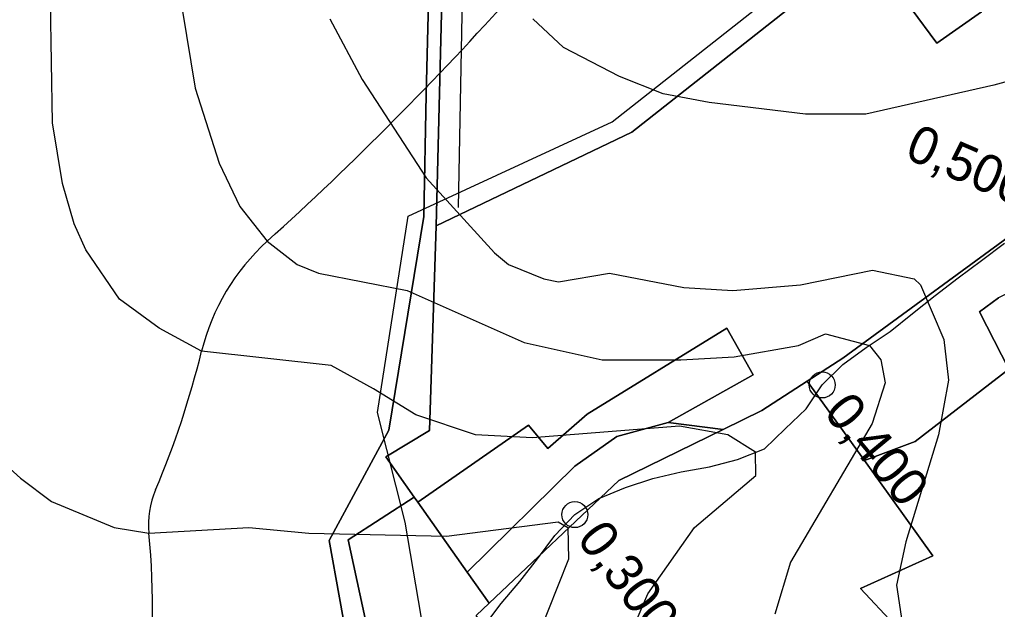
# Model space of a CAD drawing. Extents: x -510989 to -501240, y -1184665 to -1176089.
# Drawn here: x -510047.2 to -509708.8, y -1177583.4 to -1177379.3 of the extents above; entities that cross this region are included whole.
import ezdxf

# ---------------------------------------------------------------- set-up
doc = ezdxf.new("R2010")
doc.units = 0
for name, color, linetype in [('lesni_pozemek', 7, 'Continuous'), ('NAVRH_interakcni_prvky', 7, 'Continuous'), ('NAVRH_rozvodnice', 7, 'Continuous'), ('orna_puda', 7, 'Continuous'), ('ostatni_plocha_x_neplodna_puda', 7, 'Continuous'), ('ostatni_plocha_x_ostatni_komunikace', 7, 'Continuous'), ('STAV_systematicke_odvodneni', 7, 'Continuous'), ('trasovani_toku', 7, 'Continuous'), ('trvaly_travni_porost', 7, 'Continuous'), ('vrstevnice_01', 7, 'Continuous'), ('vrstevnice_02', 7, 'Continuous')]:
    doc.layers.add(name, color=color, linetype=linetype)

msp = doc.modelspace()

# ---------------------------------------------------------------- linework, layer by layer
at = {"layer": 'lesni_pozemek'}
for points in [[(-509631, -1177375.54), (-509666.85, -1177393), (-509662.19, -1177399.04), (-509661.92, -1177399.66), (-509680.94, -1177416.84), (-509697.38, -1177448.86), (-509762.27, -1177496.39), (-509774.65, -1177504.38), (-509790.33, -1177514.5), (-509803.69, -1177521.05), (-509822.77, -1177518.7), (-509793.37, -1177502.17), (-509802.43, -1177486.07), (-509850.77, -1177515.75), (-509864.33, -1177527.68), (-509871.08, -1177519.58), (-509909.37, -1177546.26), (-509910.59, -1177544.53), (-509920.45, -1177530.57), (-509905.31, -1177521.45), (-509903.04, -1177450.59), (-509835.36, -1177418.23), (-509751.69, -1177352.23)], [(-509738.62, -1177375.49), (-509729.77, -1177387.4), (-509714.36, -1177376.56)]]:
    msp.add_lwpolyline(points, dxfattribs=at)
msp.add_lwpolyline([(-509774.65, -1177504.38), (-509754.82, -1177531.88), (-509731.1, -1177564.78), (-509756.2, -1177576.17), (-509744.57, -1177588.61), (-509743.5, -1177592.06), (-509744.51, -1177592.95), (-509813.59, -1177626.16), (-509833.49, -1177635.63), (-509833.73, -1177635.07), (-509845.97, -1177640.31), (-509843.9, -1177645.16), (-509847.08, -1177646.52), (-509847.22, -1177643.51), (-509889.18, -1177585.43), (-509884.7, -1177581.2), (-509839.79, -1177538.76), (-509803.69, -1177521.05), (-509790.33, -1177514.5)], close=True, dxfattribs=at)
at = {"layer": 'NAVRH_interakcni_prvky'}
msp.add_line((-509892, -1177261.75), (-509895.38, -1177444.26), dxfattribs=at)
at = {"layer": 'NAVRH_rozvodnice'}
for centre, radius, start, end in [((-510726.34, -1176610.57), 1140.06, 312.13471, 318.23054), ((-509910.8, -1177512.04), 75.57, 132.1347, 166.1887), ((-510294.96, -1177417.6), 320.03, 337.1311, 346.1887), ((-509971.35, -1177554.1), 31.2, 157.1311, 185.3427), ((-510283.91, -1177583.33), 282.73, 352.9555, 5.3427), ((-509791.78, -1177499.16), 123.67, 297.3565, 320.3942)]:
    msp.add_arc(centre, radius, start, end, dxfattribs=at)
at = {"layer": 'orna_puda'}
for points in [[(-509751.69, -1177352.23), (-509835.36, -1177418.23), (-509903.04, -1177450.59), (-509898.13, -1177257.43)], [(-509903.08, -1177271.99), (-509906.47, -1177405.26), (-509907.24, -1177447.42), (-509919.35, -1177521.3), (-509940.02, -1177559.56), (-509932.88, -1177599.21), (-509966.13, -1177637.97), (-509980.54, -1177661.84), (-509986.51, -1177693.69), (-510011.12, -1177708.83), (-510046.21, -1177724.59), (-510065.83, -1177729.25), (-510067.57, -1177729.21), (-510116.51, -1177610.57), (-510123.38, -1177588.75), (-510123.04, -1177446.95), (-510102.14, -1177427.79), (-510084.34, -1177409.75), (-510084.36, -1177388.11), (-510071.74, -1177384.51), (-510072, -1177373.55)]]:
    msp.add_lwpolyline(points, dxfattribs=at)
at = {"layer": 'ostatni_plocha_x_neplodna_puda'}
for points in [[(-509636.26, -1177329.52), (-509714.36, -1177376.56), (-509729.77, -1177387.4), (-509738.62, -1177375.49), (-509736.13, -1177373.95), (-509643.81, -1177316.99)], [(-509803.69, -1177521.05), (-509839.79, -1177538.76), (-509884.7, -1177581.2), (-509892.27, -1177570.48), (-509855.08, -1177533.79), (-509840.53, -1177523.5), (-509822.77, -1177518.7)]]:
    msp.add_lwpolyline(points, close=True, dxfattribs=at)
at = {"layer": 'ostatni_plocha_x_ostatni_komunikace'}
for points in [[(-509898.13, -1177257.43), (-509903.04, -1177450.59), (-509905.31, -1177521.45), (-509920.45, -1177530.57), (-509910.59, -1177544.53), (-509933.52, -1177559.31), (-509924.48, -1177600.95)], [(-509932.88, -1177599.21), (-509940.02, -1177559.56), (-509919.35, -1177521.3), (-509907.24, -1177447.42), (-509906.47, -1177405.26), (-509903.08, -1177271.99)]]:
    msp.add_lwpolyline(points, dxfattribs=at)
at = {"layer": 'STAV_systematicke_odvodneni'}
for p, q in [((-509842.09, -1177414.7), (-509753.36, -1177344.65)), ((-509912.65, -1177447.32), (-509842.09, -1177414.7)), ((-509923.34, -1177515.24), (-509912.65, -1177447.32)), ((-509913.72, -1177553.2), (-509923.34, -1177515.24)), ((-509902.49, -1177619.51), (-509913.72, -1177553.2))]:
    msp.add_line(p, q, dxfattribs=at)
at = {"layer": 'trasovani_toku'}
for p, q in [((-509714.35, -1177462.66), (-509706.4, -1177456.59)), ((-509722.38, -1177468.62), (-509714.35, -1177462.66)), ((-509730.31, -1177474.71), (-509722.38, -1177468.62)), ((-509738.15, -1177480.92), (-509730.31, -1177474.71)), ((-509745.96, -1177487.17), (-509738.15, -1177480.92)), ((-509754.28, -1177492.72), (-509745.96, -1177487.17)), ((-509762.35, -1177498.62), (-509754.28, -1177492.72)), ((-509769.42, -1177505.7), (-509762.35, -1177498.62)), ((-509774.99, -1177514), (-509769.42, -1177505.7)), ((-509782.25, -1177520.87), (-509774.99, -1177514)), ((-509789.42, -1177527.85), (-509782.25, -1177520.87)), ((-509798.75, -1177531.43), (-509789.42, -1177527.85)), ((-509808.4, -1177534.06), (-509798.75, -1177531.43)), ((-509818.25, -1177535.78), (-509808.4, -1177534.06)), ((-509837.49, -1177541.15), (-509827.99, -1177538.03)), ((-509827.99, -1177538.03), (-509818.25, -1177535.78)), ((-509846.76, -1177544.93), (-509837.49, -1177541.15)), ((-509855.02, -1177550.56), (-509846.76, -1177544.93)), ((-509861.91, -1177557.8), (-509855.02, -1177550.56)), ((-509867.92, -1177565.8), (-509861.91, -1177557.8)), ((-509874.1, -1177573.66), (-509867.92, -1177565.8)), ((-509880.56, -1177581.29), (-509874.1, -1177573.66)), ((-509886.58, -1177589.28), (-509880.56, -1177581.29))]:
    msp.add_line(p, q, dxfattribs=at)
for centre in [(-509769.42, -1177505.7), (-509855.02, -1177550.56)]:
    msp.add_circle(centre, 4.5, dxfattribs=at)
at = {"layer": 'trvaly_travni_porost'}
for points in [[(-509661.92, -1177399.66), (-509643.12, -1177442.55), (-509633.68, -1177445.21), (-509611.17, -1177445.97), (-509589.76, -1177453.23), (-509546.91, -1177453.53), (-509568.76, -1177455.65), (-509586.79, -1177457.4), (-509599.68, -1177456.28), (-509596.6, -1177463.39), (-509627.43, -1177456.33), (-509637.9, -1177458.29), (-509642.03, -1177451.61), (-509660.52, -1177452), (-509708.48, -1177475.5), (-509715.05, -1177480.43), (-509704.91, -1177500.28), (-509737.25, -1177525.22), (-509754.82, -1177531.88), (-509774.65, -1177504.38), (-509762.27, -1177496.39), (-509697.38, -1177448.86), (-509680.94, -1177416.84)], [(-509793.37, -1177502.17), (-509822.77, -1177518.7), (-509840.53, -1177523.5), (-509855.08, -1177533.79), (-509892.27, -1177570.48), (-509909.37, -1177546.26), (-509871.08, -1177519.58), (-509864.33, -1177527.68), (-509850.77, -1177515.75), (-509802.43, -1177486.07)]]:
    msp.add_lwpolyline(points, close=True, dxfattribs=at)
for points in [[(-509678.3, -1177635.13), (-509719.86, -1177643.27), (-509792.23, -1177678.3), (-509813.59, -1177626.16), (-509744.51, -1177592.95), (-509743.5, -1177592.06), (-509744.57, -1177588.61), (-509756.2, -1177576.17), (-509731.1, -1177564.78), (-509754.82, -1177531.88), (-509737.25, -1177525.22), (-509704.91, -1177500.28), (-509715.05, -1177480.43), (-509708.48, -1177475.5)], [(-509924.48, -1177600.95), (-509933.52, -1177559.31), (-509910.59, -1177544.53), (-509909.37, -1177546.26), (-509892.27, -1177570.48), (-509884.7, -1177581.2), (-509889.18, -1177585.43)]]:
    msp.add_lwpolyline(points, dxfattribs=at)
at = {"layer": 'vrstevnice_01'}
for points in [[(-509993.81, -1177358), (-509986.41, -1177403), (-509978.09, -1177429), (-509970.91, -1177444), (-509961.5, -1177456), (-509951.09, -1177464), (-509943.69, -1177467), (-509913, -1177473), (-509872.59, -1177491), (-509845.59, -1177497), (-509818.31, -1177497), (-509799.91, -1177496), (-509777.69, -1177492), (-509768.31, -1177488), (-509753.09, -1177492), (-509749.19, -1177497), (-509747.69, -1177505), (-509752.19, -1177519), (-509780.41, -1177567), (-509785.81, -1177585)], [(-509655.19, -1177387), (-509710.09, -1177402), (-509754.31, -1177412), (-509775.19, -1177412), (-509808.5, -1177408), (-509824.5, -1177405), (-509839.59, -1177399), (-509858.91, -1177389), (-509869.59, -1177379)], [(-510059.09, -1177527), (-510046.81, -1177538), (-510036.09, -1177546), (-510014.41, -1177555), (-510002.41, -1177557), (-509967.81, -1177555), (-509947.09, -1177557), (-509899.41, -1177558), (-509860.81, -1177553), (-509857.41, -1177555), (-509857.19, -1177566), (-509871.5, -1177602), (-509874.5, -1177614), (-509873.91, -1177636), (-509864.31, -1177662), (-509854.19, -1177680), (-509839.41, -1177701), (-509830.19, -1177712), (-509824.59, -1177716), (-509798.41, -1177725), (-509768.31, -1177727), (-509712.91, -1177726), (-509697.5, -1177729)]]:
    msp.add_lwpolyline(points, dxfattribs=at)
at = {"layer": 'vrstevnice_02'}
for points in [[(-509834.5, -1177589), (-509829.81, -1177578), (-509813.59, -1177555), (-509792.41, -1177537), (-509792.5, -1177529), (-509802.09, -1177523), (-509818.81, -1177520), (-509869.69, -1177524), (-509889.41, -1177523), (-509910, -1177516), (-509924.69, -1177507), (-509939.31, -1177499), (-509984.19, -1177494), (-509998.91, -1177486), (-510012.59, -1177476), (-510024.19, -1177459), (-510028.31, -1177450), (-510032.31, -1177436), (-510035.81, -1177415), (-510036.5, -1177373)], [(-509939.81, -1177379), (-509928.59, -1177400), (-509906.5, -1177434), (-509882.81, -1177460), (-509878, -1177464), (-509865.81, -1177469), (-509860.69, -1177470), (-509843, -1177467), (-509817.31, -1177472), (-509800.31, -1177473), (-509777, -1177471), (-509752, -1177466), (-509737.59, -1177469), (-509735.41, -1177471), (-509727.31, -1177490), (-509725.69, -1177504), (-509729.19, -1177523), (-509740.5, -1177560), (-509743.69, -1177575), (-509739.81, -1177601), (-509730.09, -1177617), (-509720, -1177627), (-509692.31, -1177648)]]:
    msp.add_lwpolyline(points, dxfattribs=at)

# ---------------------------------------------------------------- texts
at = {"layer": 'trasovani_toku'}
for s, rotation, p in [('0,500', 336.6357, (-509741.37, -1177426.96)), ('0,400', 309.5989, (-509769.32, -1177515.29)), ('0,300', 307.189, (-509854.7, -1177559.05))]:
    msp.add_text(s, height=13, rotation=rotation, dxfattribs=at).set_placement(p)

doc.saveas('drawing.dxf')
